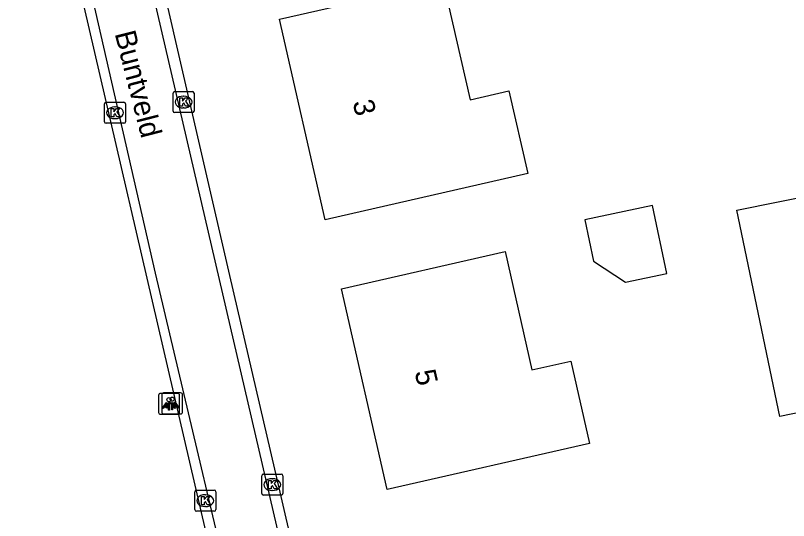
# Model space of a CAD drawing. Extents: x 162675 to 163482, y 379761 to 381227.
# Drawn here: x 162869.27 to 162906.11, y 380692.76 to 380716.81 of the extents above; entities that cross this region are included whole.
import ezdxf

# ---------------------------------------------------------------- set-up
doc = ezdxf.new("R2010")
doc.units = 0
for name, color, linetype in [('IMGEO_Kolk', 7, 'Continuous'), ('IMGEO_Lichtpunt', 7, 'Continuous'), ('IMGEO_Openbare_ruimte_label', 7, 'Continuous'), ('IMGEO_Pand', 7, 'Continuous'), ('IMGEO_Pand_nummerreeks', 7, 'Continuous'), ('IMGEO_Rijbaan_lokaal_gesloten', 7, 'Continuous'), ('IMGEO_Rijbaan_lokaal_open', 7, 'Continuous')]:
    doc.layers.add(name, color=color, linetype=linetype)

msp = doc.modelspace()

# ---------------------------------------------------------------- linework, layer by layer
at = {"layer": 'IMGEO_Kolk'}
for p, q in [((162876.781, 380712.258), (162876.781, 380713.11)), ((162876.856, 380713.184), (162877.708, 380713.184)), ((162877.269, 380712.964), (162877.294, 380712.964)), ((162877.782, 380713.11), (162877.782, 380712.258)), ((162873.511, 380711.749), (162873.511, 380712.601)), ((162873.586, 380712.675), (162874.438, 380712.675)), ((162874.512, 380712.601), (162874.512, 380711.749)), ((162873.999, 380712.455), (162874.024, 380712.455)), ((162877.292, 380712.404), (162877.267, 380712.404)), ((162874.022, 380711.895), (162873.997, 380711.895)), ((162877.708, 380712.184), (162876.856, 380712.184)), ((162874.438, 380711.675), (162873.586, 380711.675)), ((162881.082, 380694.969), (162881.934, 380694.969)), ((162881.007, 380694.043), (162881.007, 380694.895)), ((162881.495, 380694.749), (162881.52, 380694.749)), ((162882.008, 380694.895), (162882.008, 380694.043)), ((162877.889, 380694.205), (162878.741, 380694.205)), ((162881.518, 380694.189), (162881.493, 380694.189)), ((162877.814, 380693.279), (162877.814, 380694.131)), ((162878.302, 380693.985), (162878.327, 380693.985)), ((162878.815, 380694.131), (162878.815, 380693.279)), ((162881.934, 380693.969), (162881.082, 380693.969)), ((162878.325, 380693.425), (162878.3, 380693.425)), ((162878.741, 380693.205), (162877.889, 380693.205))]:
    msp.add_line(p, q, dxfattribs=at)
for points in [[(162876.781, 380712.258), (162876.781, 380713.11)], [(162876.856, 380713.184), (162877.708, 380713.184)], [(162877.782, 380713.11), (162877.782, 380712.258)], [(162873.511, 380711.749), (162873.511, 380712.601)], [(162873.586, 380712.675), (162874.438, 380712.675)], [(162874.512, 380712.601), (162874.512, 380711.749)], [(162877.102, 380712.884), (162877.225, 380712.884), (162877.225, 380712.733), (162877.355, 380712.884), (162877.519, 380712.884), (162877.373, 380712.733), (162877.526, 380712.484), (162877.374, 380712.484), (162877.289, 380712.648), (162877.225, 380712.581), (162877.225, 380712.484), (162877.102, 380712.484), (162877.102, 380712.884)], [(162873.832, 380712.375), (162873.955, 380712.375), (162873.955, 380712.224), (162874.085, 380712.375), (162874.249, 380712.375), (162874.103, 380712.224), (162874.256, 380711.975), (162874.104, 380711.975), (162874.019, 380712.139), (162873.955, 380712.072), (162873.955, 380711.975), (162873.832, 380711.975), (162873.832, 380712.375)], [(162877.708, 380712.184), (162876.856, 380712.184)], [(162874.438, 380711.675), (162873.586, 380711.675)], [(162881.082, 380694.969), (162881.934, 380694.969)], [(162881.007, 380694.043), (162881.007, 380694.895)], [(162881.328, 380694.669), (162881.451, 380694.669), (162881.451, 380694.518), (162881.581, 380694.669), (162881.745, 380694.669), (162881.599, 380694.518), (162881.752, 380694.269), (162881.6, 380694.269), (162881.515, 380694.433), (162881.451, 380694.366), (162881.451, 380694.269), (162881.328, 380694.269), (162881.328, 380694.669)], [(162882.008, 380694.895), (162882.008, 380694.043)], [(162877.889, 380694.205), (162878.741, 380694.205)], [(162877.814, 380693.279), (162877.814, 380694.131)], [(162878.135, 380693.905), (162878.258, 380693.905), (162878.258, 380693.754), (162878.388, 380693.905), (162878.552, 380693.905), (162878.406, 380693.754), (162878.559, 380693.505), (162878.407, 380693.505), (162878.322, 380693.669), (162878.258, 380693.602), (162878.258, 380693.505), (162878.135, 380693.505), (162878.135, 380693.905)], [(162878.815, 380694.131), (162878.815, 380693.279)], [(162881.934, 380693.969), (162881.082, 380693.969)], [(162878.741, 380693.205), (162877.889, 380693.205)]]:
    msp.add_lwpolyline(points, dxfattribs=at)
for centre, start, end in [((162876.858, 380713.108), 91.552, 178.448), ((162876.858, 380713.108), 91.552, 178.448), ((162877.706, 380713.108), 1.552, 88.448), ((162877.706, 380713.108), 1.552, 88.448), ((162873.588, 380712.599), 91.552, 178.448), ((162873.588, 380712.599), 91.552, 178.448), ((162874.436, 380712.599), 1.552, 88.448), ((162874.436, 380712.599), 1.552, 88.448), ((162876.858, 380712.26), 181.552, 268.448), ((162876.858, 380712.26), 181.552, 268.448), ((162877.706, 380712.26), 271.552, 358.448), ((162877.706, 380712.26), 271.552, 358.448), ((162873.588, 380711.751), 181.552, 268.448), ((162873.588, 380711.751), 181.552, 268.448), ((162874.436, 380711.751), 271.552, 358.448), ((162874.436, 380711.751), 271.552, 358.448), ((162881.084, 380694.893), 91.552, 178.448), ((162881.084, 380694.893), 91.552, 178.448), ((162881.932, 380694.893), 1.552, 88.448), ((162881.932, 380694.893), 1.552, 88.448), ((162877.891, 380694.129), 91.552, 178.448), ((162877.891, 380694.129), 91.552, 178.448), ((162878.739, 380694.129), 1.552, 88.448), ((162878.739, 380694.129), 1.552, 88.448), ((162881.084, 380694.045), 181.552, 268.448), ((162881.084, 380694.045), 181.552, 268.448), ((162881.932, 380694.045), 271.552, 358.448), ((162881.932, 380694.045), 271.552, 358.448), ((162877.891, 380693.281), 181.552, 268.448), ((162877.891, 380693.281), 181.552, 268.448), ((162878.739, 380693.281), 271.552, 358.448), ((162878.739, 380693.281), 271.552, 358.448)]:
    msp.add_arc(centre, 0.0765, start, end, dxfattribs=at)
for centre, major_axis, ratio, start_param, end_param in [((162877.268, 380712.684), (-0.387, 0.002), 0.722429, 4.712389, 7.853982), ((162877.293, 380712.684), (-0.39, 0.002), 0.717154, 1.570796, 4.712389), ((162873.998, 380712.175), (-0.387, 0.002), 0.722429, 4.712389, 7.853982), ((162874.023, 380712.175), (-0.39, 0.002), 0.717154, 1.570796, 4.712389), ((162881.494, 380694.469), (-0.387, 0.002), 0.722429, 4.712389, 7.853982), ((162881.519, 380694.469), (-0.39, 0.002), 0.717154, 1.570796, 4.712389), ((162878.301, 380693.705), (-0.387, 0.002), 0.722429, 4.712389, 7.853982), ((162878.326, 380693.705), (-0.39, 0.002), 0.717154, 1.570796, 4.712389)]:
    msp.add_ellipse(centre, major_axis=major_axis, ratio=ratio, start_param=start_param, end_param=end_param, dxfattribs=at)
at = {"layer": 'IMGEO_Lichtpunt'}
for p, q in [((162876.089, 380698.718), (162876.089, 380697.911)), ((162876.089, 380698.718), (162876.089, 380697.911)), ((162876.991, 380698.813), (162876.183, 380698.813)), ((162876.991, 380698.813), (162876.183, 380698.813)), ((162876.236, 380698.741), (162876.236, 380697.934)), ((162876.236, 380698.741), (162876.236, 380697.934)), ((162877.138, 380698.836), (162876.33, 380698.836)), ((162877.138, 380698.836), (162876.33, 380698.836)), ((162877.085, 380697.911), (162877.085, 380698.718)), ((162877.085, 380697.911), (162877.085, 380698.718)), ((162877.232, 380697.934), (162877.232, 380698.741)), ((162877.232, 380697.934), (162877.232, 380698.741)), ((162876.183, 380697.817), (162876.991, 380697.817)), ((162876.183, 380697.817), (162876.991, 380697.817)), ((162876.33, 380697.84), (162877.138, 380697.84)), ((162876.33, 380697.84), (162877.138, 380697.84))]:
    msp.add_line(p, q, dxfattribs=at)
for points in [[(162876.463, 380698.382), (162876.502, 380698.354), (162876.314, 380698.092), (162876.276, 380698.119), (162876.463, 380698.382)], [(162876.61, 380698.405), (162876.649, 380698.377), (162876.461, 380698.115), (162876.423, 380698.142), (162876.61, 380698.405)], [(162876.565, 380698.334), (162876.612, 380698.334), (162876.612, 380698.012), (162876.565, 380698.012), (162876.565, 380698.334)], [(162876.675, 380698.354), (162876.713, 380698.381), (162876.9, 380698.119), (162876.861, 380698.091), (162876.675, 380698.354)], [(162876.712, 380698.357), (162876.759, 380698.357), (162876.759, 380698.035), (162876.712, 380698.035), (162876.712, 380698.357)], [(162876.822, 380698.377), (162876.86, 380698.404), (162877.047, 380698.142), (162877.008, 380698.114), (162876.822, 380698.377)]]:
    msp.add_lwpolyline(points, dxfattribs=at)
for centre in [(162876.588, 380698.516), (162876.735, 380698.539)]:
    msp.add_circle(centre, 0.0994, dxfattribs=at)
for centre, start, end in [((162876.183, 380698.718), 90, 180), ((162876.183, 380698.718), 90, 180), ((162876.33, 380698.741), 90, 180), ((162876.33, 380698.741), 90, 180), ((162876.991, 380698.718), 0, 90), ((162876.991, 380698.718), 0, 90), ((162877.138, 380698.741), 0, 90), ((162877.138, 380698.741), 0, 90), ((162876.183, 380697.911), 180, 270), ((162876.183, 380697.911), 180, 270), ((162876.33, 380697.934), 180, 270), ((162876.33, 380697.934), 180, 270), ((162876.991, 380697.911), 270, 0), ((162876.991, 380697.911), 270, 360), ((162877.138, 380697.934), 270, 0), ((162877.138, 380697.934), 270, 360)]:
    msp.add_arc(centre, 0.0946, start, end, dxfattribs=at)
at = {"layer": 'IMGEO_Pand'}
for points in [[(162893.68, 380709.286), (162884.029, 380707.079), (162881.844, 380716.631), (162889.643, 380718.415), (162890.929, 380712.79), (162892.781, 380713.214), (162893.68, 380709.286)], [(162917.388, 380704.877), (162914.352, 380704.252), (162914.761, 380702.264), (162915.291, 380699.688), (162905.694, 380697.713), (162903.651, 380707.533), (162913.177, 380709.463), (162912.593, 380712.303), (162915.727, 380712.948), (162917.388, 380704.877)], [(162896.393, 380707.078), (162896.806, 380705.111), (162898.334, 380704.114), (162900.301, 380704.528), (162899.622, 380707.757), (162896.393, 380707.078)], [(162896.629, 380696.426), (162886.976, 380694.229), (162884.799, 380703.787), (162892.6, 380705.563), (162893.881, 380699.937), (162895.734, 380700.355), (162896.629, 380696.426)]]:
    msp.add_lwpolyline(points, dxfattribs=at)
at = {"layer": 'IMGEO_Rijbaan_lokaal_gesloten'}
for points in [[(162869.725, 380731.638), (162875.926, 380704.534), (162880.576, 380684.855)], [(162883.288, 380685.726), (162872.96, 380730.208)]]:
    msp.add_lwpolyline(points, dxfattribs=at)
at = {"layer": 'IMGEO_Rijbaan_lokaal_open'}
for points in [[(162869.268, 380731.287), (162880.059, 380684.786)], [(162873.405, 380730.498), (162874.095, 380727.69), (162879.473, 380704.423), (162881.618, 380695.209), (162883.858, 380685.538)]]:
    msp.add_lwpolyline(points, dxfattribs=at)

# ---------------------------------------------------------------- texts
at = {"layer": 'IMGEO_Openbare_ruimte_label'}
msp.add_text('Buntveld', height=1, rotation=284.3558, dxfattribs=at).set_placement((162873.99, 380715.952))
at = {"layer": 'IMGEO_Pand_nummerreeks'}
for s, rotation, p in [('3', 282.8846, (162885.331, 380712.686)), ('5', 282.8312, (162888.283, 380699.836))]:
    msp.add_text(s, height=1, rotation=rotation, dxfattribs=at).set_placement(p)

doc.saveas('drawing.dxf')
